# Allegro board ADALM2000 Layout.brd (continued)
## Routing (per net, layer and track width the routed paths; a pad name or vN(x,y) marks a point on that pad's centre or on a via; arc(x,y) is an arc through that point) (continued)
EN_SC2_CAL2: length 63.2
  TOP w0.102: U15.8 56.2,37.5 56.3,37.6 56.3,39.25 54.46,41.09 54.46,41.73 55.15,42.43 v1(55.15,42.87)
  L5_SIG w0.114: v1(24.48,52.91) 23.85,52.27 23.85,51.13 24.36,50.62 24.36,47.57 24.61,47.32 v1(24.61,46.68)
  L6_SIG w0.114: v1(55.15,42.87) 55.6,43.32 55.6,48.46 55.03,49.03 52.11,49.03 48.61,52.52 48.61,54.56 47.98,55.19 46.84,55.19 46.58,55.45 46.58,56.46 46.14,56.91 43.79,56.91 42.9,57.79 42.9,59.13 42.01,60.02 37.56,60.02 34.9,57.35 33.3,57.35 29.36,53.41 24.99,53.41 v1(24.48,52.91)
  BOTTOM w0.102: v1(24.61,46.68) 26.01,46.68 26.01,46.68 A2.16
EN_SC2_HG: length 56
  TOP w0.102: U15.14 53.35,35.85 51.85,37.35 51.85,41.41 v1(51.53,41.73) ; A1.9 29.81,47.71 v1(29.56,47.95) ; A1.1 v1(24.61,40.71)
  L5_SIG w0.114: v1(24.86,48.21) 25.12,47.95 25.12,41.22 v1(24.61,40.71)
  L6_SIG w0.114: v1(51.53,41.73) 50.65,42.62 50.65,45.41 50.01,46.05 48.87,46.05 47.22,47.7 47.22,49.1 45.82,50.49 41.5,50.49 39.85,52.14 38.96,52.14 37.95,53.16 30.96,53.16 30.26,52.46 30.26,50.68 29.31,49.73 29.31,48.71 29.56,48.46 v1(29.56,47.95) 29.18,47.57 25.5,47.57 v1(24.86,48.21)
EN_SC2_LG: length 49.3
  TOP w0.102: v1(23.47,47.57) 24.85,47.57 25.26,47.17 A1.16 ; v1(52.49,41.73) 52.49,41.29 52.17,40.97 52.17,37.41 53.33,36.25 U15.13
  TOP w0.203: A1.8 v1(29.81,41.92)
  L6_SIG w0.114: v1(52.49,41.73) 51.47,40.71 48.61,40.71 47.28,42.05 46.33,42.05 46.01,41.73 43.41,41.73 42.07,43.06 39.34,43.06 38.9,42.62 38.9,41.67 38.52,41.29 37.12,41.29 36.74,40.9 31.91,40.9 31.47,40.46 30.2,40.46 29.81,40.85 v1(29.81,41.92)
  BOTTOM w0.102: v1(23.47,47.57) 23.59,47.57 24.1,47.06 24.1,46.43 23.21,45.54 23.21,44.02 23.59,43.63 28.09,43.63 v1(29.81,41.92)
EN_SC_CAL1: length 65.6
  TOP w0.102: v1(54.2,43.51) 54.71,43 54.71,42.36 54.2,41.86 54.2,40.97 55.98,39.19 55.98,37.73 55.8,37.55 U15.9
  L6_SIG w0.114: v1(24.48,52.02) 25.37,52.91 29.44,52.91 33.5,56.97 35.02,56.97 37.69,59.64 41.88,59.64 42.52,59 42.52,57.6 43.53,56.59 45.95,56.59 46.2,56.33 46.2,55.32 46.71,54.81 47.85,54.81 48.23,54.43 48.23,52.4 52.55,48.08 52.55,47.44 51.53,46.43 51.53,44.52 52.55,43.51 v1(54.2,43.51)
  BOTTOM w0.102: A2.9 31.46,47.84 31.09,48.21 31.09,49.86 30.83,50.11 27.79,50.11 26.91,50.99 A2.1 24.99,52.52 v1(24.48,52.02)
EN_USR_POW_NEG: length 66
  TOP w0.102: U15.2 57.72,34.65 57.96,34.41 57.96,32.2 58.14,32.03 58.14,31.54 57.78,31.19 57.03,31.19 v1(56.61,30.77)
  L5_SIG w0.114: v1(56.61,30.77) 55.6,29.76 55.6,22.55 54.58,21.54 52.8,21.54 50.9,19.63 50.9,17.85 46.2,13.15 43.6,13.15 39.79,9.34 31.6,9.34 30.58,10.36 21.05,10.36 20.04,11.38 20.04,14.55 20.42,14.93 21.31,14.93 21.56,14.68 v1(24.36,14.68)
  BOTTOM w0.102: v1(24.36,14.68) 24.36,13.47 Q5.2
EN_USR_POW_POS: length 60.9
  TOP w0.102: v1(57.57,31.76) 57.57,32.33 57.35,32.55 U15.1
  L5_SIG w0.114: v1(20.67,14.3) 20.67,13.79 20.42,13.54 20.42,11.76 21.44,10.74 30.83,10.74 31.85,9.73 39.66,9.73 43.47,13.54 46.07,13.54 50.52,17.98 50.52,19.76 52.8,22.04 v1(53.31,22.04)
  BOTTOM w0.102: Q4.2 20.67,13.47 v1(20.67,14.3) ; v1(53.31,22.04) 54.58,23.31 58.65,23.31 58.96,23.63 58.96,27.7 57.69,28.97 57.69,31.32 v1(57.57,31.76)
ENABLE_POW_NEG: length 19.2
  TOP w0.102: A14.5 v1(15.4,5.92)
  BOTTOM w0.102: v1(15.4,5.92) 15.4,5.22 16.36,4.26 22.45,4.26 24.1,5.92 24.1,8.46 25.12,9.47 26.01,9.47 26.18,9.65 R147.1 26.18,12.33 Q5.3
ENABLE_POW_POS: length 13
  TOP w0.254: A12.5 v1(15.4,11.63)
  BOTTOM w0.102: v1(15.4,11.63) 15.4,10.68 16.1,9.98 20.93,9.98 22.32,11.38 22.32,12.15 Q4.3 22.88,12.71 R129.1
FB_1V0_D: length 12.5
  TOP w0.254: U6.32 v1(83.32,56.21)
  L5_SIG w0.305: v1(83.32,56.21) 83.32,49.69 84.17,48.84 v1(86.46,48.84)
  BOTTOM w0.203: v1(86.46,48.84) 85.87,48.84 R207.2
  BOTTOM w0.254: v1(83.32,56.21) 83.03,55.92 R208.1
FB_1V8: length 10.1
  TOP w0.203: U518.32 98.24,53.26 98.45,53.46 v2(98.45,54.05)
  L5_SIG w0.203: v1(98.91,47.06) 98.45,47.52 v2(98.45,54.05)
  BOTTOM w0.203: R765.1 98.4,46.22 98.4,46.56 v1(98.91,47.06) ; v2(98.45,54.05) R766.2
FB_1V35: length 16
  TOP w0.102: U518.9 92.84,53.26 92.68,53.41 v2(92.3,53.41)
  L5_SIG w0.203: v1(88.62,42.87) 89.38,42.87 93.44,46.94 93.44,52.65 92.68,53.41 v2(92.3,53.41)
  BOTTOM w0.102: R764.1 v2(92.3,53.41)
  BOTTOM w0.203: R763.2 v1(88.62,42.87)
FB_3V3_D: length 10.7
  TOP w0.254: U6.9 78.42,56.12 v1(78.33,56.21)
  L5_SIG w0.305: v1(75.86,49.22) 76.43,49.79 76.43,50.37 78.33,52.27 v1(78.33,56.21)
  BOTTOM w0.203: v1(75.86,49.22) 76.25,48.83 R205.2 ; R206.1 v1(78.33,56.21)
IN_SC1_N: length 15.1
  TOP w0.102: C72.1 18.32,56.72 R16.1 17.35,55.74 9.07,55.74 8.14,54.81 8.14,53.22 P1.1
IN_SC1_P: length 15
  TOP w0.102: P1.2 9.19,53.16 8.74,53.16 8.47,53.42 8.47,54.67 9.21,55.41 17.35,55.41 R19.1 18.32,54.43 C75.1
IN_SC2_N: length 15.3
  TOP w0.102: P1.3 8.25,49.02 8.43,49.02 8.97,48.49 11.63,48.49 16.65,43.47 17.39,43.47 18.07,42.78 R41.1 18.07,41.48 C129.1
IN_SC2_P: length 15.3
  TOP w0.102: P1.4 8.91,49.91 8.69,49.68 8.69,49.23 9.1,48.82 11.77,48.82 16.79,43.8 17.35,43.8 R44.1 18.32,44.78 C132.1
JTAG_TCK: length 35.4
  TOP w0.102: v1(60.3,6.17) 59.66,5.53 P510.4 ; U511.G9 82.03,25.93 77.84,21.74 77.69,21.74 76.33,20.38 75.61,20.38 69.66,14.42 66.52,14.42 v1(66.14,14.81)
  L5_SIG w0.114: v1(60.3,6.17) 61.69,6.17 63.73,8.2 63.73,10.36 64.74,11.38 64.74,13.41 v1(66.14,14.81)
JTAG_TDI: length 38.4
  TOP w0.102: v1(62.84,6.17) 62.2,5.53 P510.8 ; U511.L7 v2(85.99,27.62)
  L5_SIG w0.114: v2(85.99,27.62) 85.98,27.62 85.43,27.62 83.58,25.78 82.03,25.78 78.92,22.67 76.67,22.67 72.11,18.11 68.55,18.11 66.65,16.2 66.65,14.17 66.01,13.54 66.01,11 64.11,9.09 64.11,7.44 v1(62.84,6.17)
JTAG_TDO: length 39.3
  TOP w0.102: P510.6 60.93,6.8 v1(62.84,8.71) ; 84.85,28.19 v2(85.42,28.19)
  L5_SIG w0.114: v1(62.84,8.71) 62.84,9.98 64.36,11.5 64.36,14.46 72.59,22.68 73.63,22.68 74.01,22.3 74.78,22.3 75.66,23.19 76.43,23.19 76.55,23.06 78.88,23.06 81.89,26.06 82.73,26.06 84.86,28.19 85.42,28.19 v2(85.42,28.19)
JTAG_TMS: length 41.3
  TOP w0.102: P510.2 58.39,6.8 v1(60.3,8.71) ; U511.L9 v2(84.85,28.75)
  L5_SIG w0.114: v2(84.85,28.75) 83.16,28.75 77.72,23.31 76.81,23.31 76.05,24.08 74.39,24.08 73.79,23.47 72.84,23.47 63.98,14.61 63.98,12.9 62.2,11.12 62.2,9.47 61.44,8.71 v1(60.3,8.71)
LOOP_FILT: length 12.8
  TOP w0.203: v1(67.54,57.73) 67.32,57.51 U14.24
  TOP w0.305: R86.1 70.08,63.62 C223.1 70.15,64.67 R6.1 v1(71.09,63.95)
  BOTTOM w0.305: v1(67.54,57.73) 67.54,62.68 68.81,63.95 v1(71.09,63.95)
MASTER_CLK_N: length 15.5
  TOP w0.102: C237.2 73.84,60.45 74.34,59.94 74.34,58.81 70.59,55.06 67.19,55.06 66.59,54.46 U2.56
MASTER_CLK_P: length 15.4
  TOP w0.102: C236.2 73.02,59.59 73.12,59.69 73.12,60.02 73.23,60.12 73.7,60.12 74.01,59.8 74.01,58.95 70.46,55.4 67.05,55.4 66.26,54.6 66.26,52.34 66.09,52.17 U2.57
MUX_EN: length 17.9
  TOP w0.102: v1(34.25,36.01) 35.02,36.01 36.37,37.36 R47.2
  L5_SIG w0.114: v1(34.9,44.52) 35.28,44.14 35.28,36.4 34.9,36.01 v1(34.25,36.01)
  BOTTOM w0.102: U9.16 34.81,35.97 34.78,36 34.26,36 v1(34.25,36.01) ; U8.16 35.7,46.6 34.9,45.79 v1(34.9,44.52)
OFFSET_AWG1: length 3.3
  BOTTOM w0.102: U11.4 35.91,30.93 35.62,31.22 R99.1
OFFSET_AWG2: length 14.5
  TOP w0.203: v1(41.37,31.57) 42.01,32.2 42.01,32.71 41.31,33.41 41.31,35.89 40.3,36.9 36.55,36.9 35.24,35.6 R100.1
  BOTTOM w0.203: v1(41.37,31.57) 41.37,31.19 41.63,30.93 U11.11
OFFSET_SC1: length 54.8
  TOP w0.102: v2(40.36,32.59) 39.98,32.2 39.98,30.17 41.17,28.98 42.82,28.98 44.8,27 46.84,27 47.22,27.38 47.22,28.14 48.27,29.19 A6.1 48.6,29.68 48.92,29.36 R127.2 50.38,29.36 C304.2 ; R29.1 40.85,59.07 v1(40.21,59.07)
  L5_SIG w0.102: OFF_SC1.1 40.21,60.63 v1(40.21,59.07)
  L5_SIG w0.114: v1(40.21,59.07) 39.66,58.52 39.66,56.14 40.1,55.7 40.1,49.86 39.6,49.35 39.6,48.27 40.74,47.13 40.74,44.14 40.1,43.51 39.22,43.51 38.64,42.94 38.64,39.44 36.93,37.73 36.93,34.24 36.74,34.05 36.74,32.9 37.69,31.95 39.72,31.95 v2(40.36,32.59)
OFFSET_SC2: length 48.6
  TOP w0.102: R54.1 40.66,44.27 v1(40.1,44.27) ; A6.7 44.43,30.18 43.99,29.74 R128.2 43.03,29.74 C305.2 42.65,29.36 41.3,29.36 40.36,30.3 v2(40.36,31.57)
  L5_SIG w0.114: v2(40.36,31.57) 37.56,31.57 36.42,32.71 36.42,34.24 36.61,34.43 36.61,37.92 38.33,39.63 38.33,43.13 39.04,43.84 39.68,43.84 v1(40.1,44.27) 39.6,44.78 39.09,44.78 38.45,44.14 37.95,44.14 37.63,44.46 37.63,48.91 39.72,51 39.72,51.64 39.34,52.02 38.96,52.02 38.58,52.4 38.58,54.56 38.96,54.94 38.96,61.67 OFF_SC2.1
OUT_AWG1: length 26.1
  TOP w0.305: 24.04,25.85 23.99,25.81 R135.1 21.61,25.81 20.8,26.62 20.8,35.38 19.09,37.09 16.29,37.09 11.1,42.29 P1.10
OUT_AWG1_CALIB: length 35
  TOP w0.203: R197.1 R135.2 v1(22.83,26.67)
  L5_SIG w0.114: v1(22.83,26.67) 21.18,28.32 21.18,34.81 24.61,38.24 24.61,39.57 25.5,40.46 25.5,46.68 29.18,50.37 v1(32.74,50.37)
  BOTTOM w0.102: U8.3 34.06,49.8 33.5,50.37 v1(32.74,50.37)
OUT_AWG2: length 24.1
  TOP w0.305: P1.9 8.59,43.51 12.55,43.51 17.63,38.43 19.53,38.43 21.94,36.01 21.94,34.11 22.2,33.86 R134.1 22.72,33.08 23.47,32.33 23.47,31.82 R133.2
OUT_AWG2_CALIB: length 24.1
  TOP w0.203: v1(22.83,32.22) R134.2 R198.1
  BOTTOM w0.102: v1(22.83,32.22) 21.12,33.93 21.12,34.81 23.34,37.03 23.34,40.59 23.98,41.22 25.37,41.22 26.01,40.59 28.8,40.59 29.06,40.33 29.06,39.19 29.25,39 32.23,39 33.24,37.99 U9.3
PG_1P0V: length 21.7
  TOP w0.203: U6.29 83.92,54.04 84.05,54.18 85.06,54.18 v1(85.32,53.92) ; v2(99.92,51.76) 99.42,51.26 U518.28
  TOP w0.254: R89.2 v1(85.32,53.92)
  L6_SIG w0.114: v1(85.32,53.92) 86.46,53.92 87.09,54.56 93.51,54.56 93.95,54.11 97.57,54.11 98.08,53.6 98.08,52.65 98.43,52.3 99.38,52.3 v2(99.92,51.76)
PG_1P8V: length 135.3
  TOP w0.102: U12.3 45.95,11.06 v2(46.07,11.38) ; v2(55.34,20.9) 55.09,20.64 U10.6 ; U7.3 v1(36.55,15.44)
  TOP w0.203: v2(91.29,51.76) 91.79,51.26 U518.13 ; U6.13 77.44,53.54 77.32,53.67 75.28,53.67 74.52,54.43 v1(74.52,55.45) ; v2(99.16,51.76) 99.16,51.76 U518.29
  L5_SIG w0.114: v2(55.34,20.9) 54.77,20.33 52.11,20.33 51.28,19.5 51.28,17.69 46.07,12.49 v2(46.07,11.38) ; v2(82.9,38.55) 82.9,39.32 85.06,41.48 85.06,46.3 86.08,47.32 87.22,47.32 88.49,48.59 88.49,50.94 89.32,51.76 v2(91.29,51.76)
  L6_SIG w0.114: v2(46.07,11.38) 45.63,11.82 42.39,11.82 39.85,9.28 34.9,9.28 33.63,10.55 33.63,12.52 v1(36.55,15.44) ; v1(74.52,55.45) 76.93,55.45 78.08,54.3 78.08,52.52 79.35,51.25 90.78,51.25 v2(91.29,51.76) 91.79,52.27 92.75,52.27 94.08,53.6 97.32,53.6 97.64,53.29 97.64,52.52 98.4,51.76 v2(99.16,51.76)
  BOTTOM w0.102: v2(82.9,38.55) 81.95,38.55 80.58,39.93 75.26,39.93 74.84,39.51 74.84,37.67 70.83,33.65 68.22,33.65 66.27,31.7 66.27,31.19 66.77,30.68 66.77,28.14 60.93,22.3 58.01,22.3 56.61,20.9 v2(55.34,20.9)
  BOTTOM w0.203: v2(99.16,51.76) 98.83,51.43 R750.1
PS-SRST#: length 28.5
  TOP w0.102: v2(68.16,4.26) U508.A4 ; 78.07,24.79 78.07,24.24 75.37,21.54 74.9,21.54 74.52,21.92 74.14,21.92 R791.2 74.07,21.32 74.07,20.96 70.84,17.73 69.44,17.73 68.43,16.71 v1(68.43,16.2)
  L5_SIG w0.114: v2(68.16,4.26) 67.16,5.26 67.16,12.7 68.43,13.97 v1(68.43,16.2)
PS_MIO01_500_QSPI0_SS_B: length 31
  TOP w0.102: U511.A5 80.46,20.4 80.46,19.31 77.68,16.52 77.68,15.62 78.8,14.51 78.8,13.62 76.43,11.25 v1(75.41,11.25) ; 70.7,6.8 v2(71.2,6.3)
  L5_SIG w0.114: v2(71.2,6.3) 71.5,6.61 71.5,6.82 71.15,7.16 71.15,7.37 71.3,7.52 71.51,7.52 72.11,6.92 72.32,6.92 72.47,7.07 72.47,7.28 71.87,7.88 71.87,8.09 72.02,8.24 72.23,8.24 72.83,7.64 73.04,7.64 73.19,7.79 73.19,8 72.59,8.6 72.59,8.81 72.74,8.96 72.95,8.96 73.55,8.36 73.76,8.36 73.91,8.51 73.91,8.72 73.31,9.32 73.31,9.53 73.46,9.68 73.67,9.68 74.27,9.08 74.48,9.08 74.63,9.23 74.63,9.44 74.03,10.04 74.03,10.25 74.18,10.4 74.39,10.4 74.93,9.85 75.16,9.85 75.41,10.11 v1(75.41,11.25)
  BOTTOM w0.102: R586.2 72.05,6.3 v2(71.2,6.3)
PS_MIO02_500_QSPI0_IO0: length 27
  TOP w0.102: U511.A8 78.14,21.47 77.96,21.47 76.42,19.93 76.42,19.75 72.11,15.44 v1(71.6,15.44) ; U508.D3 v2(70.2,8.3)
  L5_SIG w0.114: v1(71.6,15.44) 71.98,15.06 71.98,14.3 71.22,13.54 71.22,13.14 71.07,12.99 70.73,12.99 70.58,12.84 70.58,12.63 70.73,12.48 71.07,12.48 71.22,12.33 71.22,12.12 71.07,11.97 70.73,11.97 70.58,11.82 70.58,11.61 70.73,11.47 71.96,11.47 72.11,11.32 72.11,11.11 71.96,10.96 70.73,10.96 70.58,10.81 70.58,10.6 70.73,10.45 71.07,10.45 71.22,10.3 71.22,9.85 70.84,9.47 69.44,9.47 69.19,9.22 69.19,8.46 69.34,8.3 v2(70.2,8.3)
  BOTTOM w0.102: R593.1 70.2,9.05 v2(70.2,8.3)
PS_MIO03_500_QSPI0_IO1: length 31.2
  TOP w0.102: U511.A7 79.16,21.96 v2(78.24,21.05) ; U508.D2 v2(71.2,8.3)
  L5_SIG w0.114: v2(71.2,8.3) 73.63,10.74 73.63,11.1 73.78,11.25 74.25,11.25 74.39,11.39 74.39,11.61 74.25,11.75 73.78,11.75 73.63,11.9 73.63,12.11 73.78,12.26 74.25,12.26 74.39,12.41 74.39,12.62 74.25,12.77 73.78,12.77 73.63,12.92 73.63,13.13 73.78,13.28 74.25,13.28 74.39,13.43 74.39,13.64 74.25,13.79 73.78,13.79 73.63,13.93 73.63,14.42 74.01,14.81 77.7,14.81 77.86,14.97 77.86,15.21 77.71,15.36 76.84,15.36 76.69,15.51 76.69,15.72 76.84,15.87 77.71,15.87 77.86,16.01 77.86,16.22 77.71,16.37 76.84,16.37 76.69,16.52 76.69,16.73 76.84,16.88 77.71,16.88 77.86,17.03 77.86,17.24 77.71,17.39 76.84,17.39 76.69,17.54 76.69,17.75 76.84,17.9 77.71,17.9 77.86,18.05 77.86,19.4 78.67,20.2 78.67,20.63 v2(78.24,21.05)
  BOTTOM w0.102: R594.1 71.2,9.07 v2(71.2,8.3)
PS_MIO04_500_QSPI0_IO2: length 30.1
  TOP w0.102: U511.C8 v2(80.9,23.66) ; U508.C4 v2(68.31,7.19)
  L5_SIG w0.114: v2(68.31,7.19) 68.68,7.57 70.46,7.57 70.71,7.82 70.71,8.58 73.12,11 73.12,13.54 72.98,13.69 72.51,13.69 72.36,13.84 72.36,14.05 72.51,14.2 72.98,14.2 73.12,14.35 73.12,14.81 73.94,15.63 74.93,15.63 75.08,15.77 75.08,15.98 74.93,16.13 73.97,16.13 73.82,16.28 73.82,16.49 73.97,16.64 74.93,16.64 77.05,18.77 77.05,20.56 78.03,21.54 79.64,21.54 80.9,22.79 v2(80.9,23.66)
  BOTTOM w0.102: v2(68.31,7.19) 69,7.19 R590.1 68.31,7.19 v2(68.31,7.19)
PS_MIO05_500_QSPI0_IO3: length 41
  TOP w0.102: v1(65.38,8.71) 66.52,7.57 66.52,3.76 64.62,1.85 61.19,1.85 60.93,2.11 P510.5 ; U511.A9 76.18,20.65 75.34,20.65 71.28,16.58 70.97,16.58 v1(70.58,16.2) ; U508.D4 v2(68.2,8.3)
  L5_SIG w0.114: v2(68.2,8.3) 68.2,8.79 68.34,8.94 68.53,8.94 68.68,9.09 68.68,9.3 68.53,9.44 68.34,9.44 68.2,9.59 68.2,9.8 68.34,9.95 68.53,9.95 68.68,10.1 68.68,10.31 68.53,10.46 68.34,10.46 68.2,10.61 68.2,11.15 68.34,11.29 69.93,11.29 70.08,11.44 70.08,11.65 69.93,11.8 68.34,11.8 68.2,11.95 68.2,12.29 70.58,14.68 v1(70.58,16.2)
  BOTTOM w0.102: v1(65.38,8.71) 66.14,8.71 66.57,8.28 R591.1 67.56,8.3 v2(68.2,8.3)
PS_MIO06_500_QSPI0_SCLK: length 28.2
  TOP w0.102: v1(69.06,15.31) 69.06,16.71 69.7,17.35 70.96,17.35 74.77,21.16 75.56,21.16 U511.A10 ; U508.B2 v2(71.2,5.3)
  L5_SIG w0.114: v2(71.2,5.3) 69.93,5.3 69.19,6.04 68.3,6.04 67.66,6.68 67.66,12.52 69.06,13.92 v1(69.06,15.31)
  BOTTOM w0.102: R583.1 72.04,5.3 v2(71.2,5.3)
PS_MIO07_500_USB_RESET_B: length 27.8
  TOP w0.102: 76.94,24.79 v2(76.45,24.31) ; U524.27 61.83,28.22 61.57,27.95 61.57,26.74 63.35,24.97 65.57,24.97 67.73,22.81 67.73,20.08 v1(68.04,19.76)
  L6_SIG w0.114: v1(68.04,19.76) 69.57,18.23 70.97,18.23 76.45,23.72 v2(76.45,24.31)
  BOTTOM w0.102: v2(76.45,24.31) 76.91,24.77 R798.2
PS_MIO28_501_USB0_D4: length 23
  TOP w0.102: U511.A15 74.79,26.04 73.56,26.04 72.74,25.22 68.93,25.22 68.3,25.85 v2(67.16,25.85) ; v2(65.81,33.47) 65.05,33.47 U524.7
  L5_SIG w0.114: v2(67.16,25.85) 67.16,26.36 66.77,26.74 66.77,30.81 66.27,31.32 66.27,32.59 65.89,32.97 65.39,32.97 65.24,33.11 65.24,33.46 65.1,33.6 64.89,33.6 64.75,33.46 64.75,33.11 64.6,32.97 64.36,32.97 64.23,33.09 64.23,33.98 64.36,34.11 65.63,34.11 65.81,33.93 v2(65.81,33.47)
PS_MIO29_501_USB0_DIR: length 29.2
  TOP w0.102: U511.D11 78.66,25.92 78.2,25.47 77.95,25.47 77.7,25.73 77.32,25.73 75.66,24.08 74.52,24.08 73.76,23.31 68.68,23.31 v2(68.17,23.82) ; U524.31 63.83,28.92 v2(64.11,28.65)
  L5_SIG w0.114: v2(68.17,23.82) 68.17,24.2 67.92,24.46 67.79,24.46 67.54,24.2 67.54,23.19 67.28,22.93 67.04,22.93 66.9,23.08 66.9,23.93 66.75,24.08 66.55,24.08 66.4,23.93 66.4,23.08 66.26,22.93 66.01,22.93 65.89,23.06 65.89,24.08 64.5,25.46 64.5,25.79 65.31,26.6 65.31,26.81 65.17,26.95 64.96,26.95 64.15,26.14 63.95,26.14 63.73,26.36 63.73,26.62 64.43,27.32 64.43,28.33 v2(64.11,28.65)
PS_MIO30_501_USB0_STP: length 24
  TOP w0.102: v2(62.96,28.08) 62.83,28.21 U524.29 ; U511.B15 75.48,27.38 74.79,27.38 74.28,26.87 73.38,26.87 72.49,25.98 69.19,25.98 68.3,26.87 67.54,26.87 66.97,27.44 64.55,27.44 64.36,27.25 64.36,26.05 64.04,25.73 v2(63.6,25.73)
  L5_SIG w0.114: v2(62.96,28.08) 62.84,28.2 62.84,29.28 62.58,29.54 62.08,29.54 61.82,29.28 61.82,26.49 62.58,25.73 v2(63.6,25.73)
PS_MIO31_501_USB0_NXT: length 29.4
  TOP w0.102: v2(66.27,25.85) 66.65,25.47 66.65,25.22 66.39,24.97 66.14,24.97 65.63,25.47 64.81,25.47 64.68,25.6 64.68,27 64.81,27.12 65.02,27.12 65.16,26.98 65.16,26.12 65.3,25.98 65.44,25.98 65.58,26.12 65.58,26.98 65.72,27.12 65.89,27.12 66.03,26.98 66.03,26.5 66.17,26.36 66.37,26.36 66.51,26.5 66.51,26.98 66.65,27.12 66.84,27.12 66.97,27 66.97,26.49 67.09,26.36 68.3,26.36 69.06,25.6 72.62,25.6 73.51,26.49 74.52,26.49 75.03,27 75.28,27 75.66,26.62 75.92,26.62 76.11,26.81 76.62,26.81 77.32,26.11 77.88,26.11 U511.C12 ; v2(66.33,30.49) 65.87,30.95 U524.2
  L5_SIG w0.114: v2(66.27,25.85) 66.33,25.92 v2(66.33,30.49)
PS_MIO32_501_USB0_D0: length 17
  TOP w0.102: v2(65.81,29.79) 66.57,29.03 67.18,29.03 67.32,29.17 67.32,29.52 67.46,29.66 67.66,29.66 67.8,29.52 67.8,29.17 67.94,29.03 68.14,29.03 68.28,29.17 68.28,29.52 68.43,29.66 68.63,29.66 68.77,29.52 68.77,29.17 68.91,29.03 70.97,29.03 71.6,29.66 75.28,29.66 75.59,29.36 76.89,29.36 U511.E15 ; U524.3 v2(65.81,31.45)
  L5_SIG w0.114: v2(65.81,31.45) v2(65.81,29.79)
PS_MIO33_501_USB0_D1: length 30.5
  TOP w0.102: v2(68.18,31.45) 67.66,30.93 66.52,30.93 66.27,31.19 66.27,31.57 65.88,31.95 U524.4 ; v2(68.17,22.81) 73.51,22.81 73.89,22.43 74.65,22.43 76.02,23.79 76.45,23.79 77.88,25.22 78.09,25.22 78.22,25.09 78.37,25.09 U511.C11
  L5_SIG w0.114: v2(68.18,31.45) 68.18,31.43 68.68,30.93 68.68,30.59 68.82,30.45 69.17,30.45 69.31,30.3 69.31,30.1 69.17,29.95 68.82,29.95 68.68,29.81 68.68,29.6 68.82,29.46 69.17,29.46 69.31,29.31 69.31,29.11 69.17,28.96 68.82,28.96 68.68,28.82 68.68,28.61 68.82,28.47 69.55,28.47 69.7,28.32 69.7,28.12 69.55,27.97 68.82,27.97 68.68,27.83 68.68,27.62 68.82,27.48 69.55,27.48 69.7,27.33 69.7,27.13 69.55,26.98 68.82,26.98 68.68,26.84 68.68,26.49 68.93,26.24 68.93,25.98 68.68,25.73 68.68,23.31 v2(68.17,22.81)
PS_MIO34_501_USB0_D2: length 20.1
  TOP w0.102: v2(65.76,28.78) 66.14,28.78 66.27,28.65 70.97,28.65 71.6,29.28 75.03,29.28 75.51,28.81 76.32,28.81 76.94,28.19 ; v2(65.81,32.45) U524.5
  L5_SIG w0.114: v2(65.76,28.78) 65.76,29.22 65.38,29.6 65.38,30.18 65.23,30.33 64.58,30.33 64.43,30.47 64.43,30.68 64.58,30.82 65.23,30.82 65.38,30.97 65.38,31.17 65.23,31.32 64.58,31.32 64.43,31.46 64.43,32.28 64.61,32.45 v2(65.81,32.45)
PS_MIO35_501_USB0_D3: length 25.8
  TOP w0.102: U511.A14 75.2,25.32 73.86,25.32 73,24.46 68.55,24.46 v2(68.17,24.84) ; v2(66.77,31.44) 66.77,31.95 66.9,32.08 68.43,32.08 68.68,32.33 68.68,32.71 68.44,32.95 U524.6
  L5_SIG w0.114: v2(68.17,24.84) 68.17,25.85 67.16,26.87 67.16,27.95 67.3,28.1 67.77,28.1 67.92,28.24 67.92,28.45 67.77,28.59 67.3,28.59 67.16,28.74 67.16,28.94 67.3,29.09 67.77,29.09 67.92,29.23 67.92,29.44 67.77,29.58 67.3,29.58 67.16,29.73 67.16,29.93 67.3,30.08 67.77,30.08 67.92,30.22 67.92,30.43 67.77,30.58 67.3,30.58 67.16,30.72 67.16,31.06 v2(66.77,31.44)
PS_MIO36_501_USB0_CLK: length 22.6
  TOP w0.102: v2(65.19,28.78) 65.19,29.09 65.38,29.28 65.38,30.3 65.22,30.45 U524.1 ; v2(67.16,24.84) 67.66,25.35 68.3,25.35 68.81,24.84 72.87,24.84 73.71,25.68 74.98,25.68 75.59,26.29 76.17,26.29 U511.B14
  L5_SIG w0.114: v2(65.19,28.78) 64.23,29.73 64.23,30.05 63.98,30.3 63.73,30.3 63.47,30.05 63.47,29.41 63.66,29.22 64.11,29.22 65.16,28.17 65.16,27.73 65.63,27.25 65.63,25.6 66.65,24.58 66.9,24.58 v2(67.16,24.84)
PS_MIO37_501_USB0_D5: length 23.2
  TOP w0.102: v2(67.66,27.38) 68.43,27.38 69.44,26.36 70.97,26.36 71.35,26.74 71.35,27.25 71.85,27.76 75.71,27.76 76.22,27.25 76.74,27.25 U511.C14 ; U524.9 64.33,34.97 64.62,35.25 65.12,35.25 v2(65.76,34.62)
  L5_SIG w0.114: v2(67.66,27.38) 67.66,26.87 67.95,26.58 68.14,26.58 68.3,26.74 68.3,30.68 67.41,31.57 67.41,31.95 66.27,33.09 66.27,34.11 v2(65.76,34.62)
PS_MIO38_501_USB0_D6: length 29.9
  TOP w0.102: v2(69.19,23.82) 69.44,24.08 73.13,24.08 74.01,24.96 75.41,24.96 75.8,25.36 U511.A13 ; v2(63.92,35.51) 63.83,35.17 U524.10
  L5_SIG w0.114: v2(69.19,23.82) 69.7,24.33 69.7,25.16 69.55,25.3 69.33,25.3 69.19,25.45 69.19,25.65 69.33,25.8 70.57,25.8 70.71,25.94 70.71,26.15 70.57,26.29 70.27,26.29 70.08,26.49 70.08,26.49 70.08,28.78 69.7,29.16 69.7,30.55 68.04,32.2 67.66,32.2 66.65,33.22 66.65,34.11 66.27,34.49 66.27,35.25 66.77,35.76 66.77,36.14 66.52,36.4 65.64,36.4 65.5,36.25 65.5,35.91 65.35,35.76 65.15,35.76 65,35.91 65,36.25 64.86,36.4 64.36,36.4 63.92,35.95 v2(63.92,35.51)
PS_MIO39_501_USB0_D7: length 21.2
  TOP w0.102: v2(66.77,34.62) 65.38,36.01 62.71,36.01 62.52,35.82 62.52,35.38 62.33,35.19 U524.13 ; U511.D14 76.89,27.62 76.1,28.41 74.79,28.41 74.65,28.27 v2(71.21,28.27)
  L5_SIG w0.114: v2(66.77,34.62) 67.03,34.36 67.03,33.35 67.66,32.71 68.04,32.71 70.08,30.68 70.08,29.4 v2(71.21,28.27)
PWR_GD_1.35V: length 53.2
  TOP w0.102: U511.C9 v2(79.2,24.23)
  TOP w0.203: v2(92.05,51.76) U518.12
  L6_SIG w0.114: v1(69.55,16.19) 70.59,17.22 71.47,17.22 78.48,24.23 v2(79.2,24.23) 79.2,24.82 81.89,27.51 82.4,27.51 85.44,30.55 85.44,31.7 87.6,33.86 90.65,33.86 91.41,34.62 91.41,35.25 91.92,35.76 91.92,42.62 92.81,43.51 92.81,51 v2(92.05,51.76)
  BOTTOM w0.102: v1(69.55,16.19) 70.09,15.66 R587.1 70.1,15.32 69,14.22 R585.2
PWR_GOOD: length 95
  TOP w0.102: v1(56.61,31.76) 56.17,31.76 55.92,31.51 54.84,31.51 53.95,32.4 53.95,33.35 54.1,33.5 U15.19 ; v2(35.53,10.61) 36.29,10.61 36.55,10.87 U7.6 ; v1(57.25,19.25) 56.86,18.87 U10.3
  TOP w0.203: v1(76.05,54.18) 77.44,54.18 77.57,54.04 U6.12
  L5_SIG w0.114: v1(58.39,39.44) 57.76,40.08 57.12,40.08 56.74,39.7 56.74,35.89 57.21,35.42 57.21,32.35 v1(56.61,31.76) 56.61,31.7 57.31,31 57.31,28.71 58.27,27.76 58.27,25.09 57.88,24.71 57.88,22.17 57.25,21.54 v1(57.25,19.25)
  L6_SIG w0.114: v2(35.53,10.61) 38.92,10.61 41.12,12.82 41.12,15.95 41.88,16.71 49.38,16.71 50.87,18.21 50.87,19.61 51.66,20.39 56.11,20.39 v1(57.25,19.25) ; v1(58.39,39.44) 57.57,40.27 57.57,41.73 58.65,42.81 58.65,50.87 59.03,51.25 67.28,51.25 68.27,52.24 70.17,52.24 71.47,53.54 75.41,53.54 v1(76.05,54.18)
  BOTTOM w0.203: v2(35.53,10.61) 35.53,9.7 R155.2
REF_1V0_AWG: length 41.4
  TOP w0.203: v1(63.09,52.5) 63.09,52.49 U2.63
  TOP w0.305: v1(49.63,28.39) 50.69,28.39 R143.2
  L5_SIG w0.203: v1(63.09,52.5) 63.7,51.89 65.63,51.89 66.58,50.94 66.58,43.44 66.14,43 57.38,43 54.9,40.52 54.9,37.16 52.42,34.68 52.42,31.19 v1(49.63,28.39)
  BOTTOM w0.305: v1(63.09,52.5) C62.1
REF_1V2: length 60.9
  TOP w0.305: A8.3 48.86,35.76 49.12,36.01 v1(49.12,36.14) ; v1(44.23,36.26) A8.5 ; C97.1 v1(25.88,21.92) 25.37,21.92 25.1,21.65 U20.10
  L5_SIG w0.508: v1(31.72,24.84) 31.72,25.85 ; 31.72,25.85 32.23,26.36 v1(32.87,26.36) 33.37,26.36 33.88,26.87 33.88,32.46 34.26,32.84 v1(34.64,32.84) ; 31.72,25.85 30.33,25.85 28.67,24.2 27.53,24.2 27.02,23.7 27.02,22.3 26.64,21.92 v1(25.88,21.92) 25.63,21.66 23.09,21.66 22.45,22.3 v1(20.42,22.3) 20.04,21.92 20.04,20.52 21.05,19.5 v1(21.05,18.23)
  L6_SIG w0.635: v1(44.23,36.26) 42.85,34.87 37.44,34.87 35.41,32.84 v1(34.64,32.84)
  BOTTOM w0.305: v1(34.64,32.84) 34.71,32.78 C296.1 35.39,32.88 U11.7 ; v1(20.42,22.3) 20.71,22.59 A13.5 ; v1(21.05,18.23) 21.57,18.75 A13.3 ; 31.41,25.16 C291.1 32.04,25.85 ; 31.81,24.2 C293.1 31.41,24.66
  BOTTOM w0.406: U19.6 32.94,25.89 ; U19.6 33.69,25.28 ; U19.6 U19.5 ; U19.6 32.19,25.28 ; U19.5 33.69,24.33 ; U19.5 32.19,24.33
  BOTTOM w0.508: v1(44.23,36.26) 44.92,36.26 45.69,37.03 48.23,37.03 v1(49.12,36.14)
REF_1V2_SC: length 70.7
  TOP w0.305: R115.1 55.08,30.81 v1(55.54,30.81)
  L5_SIG w0.508: v1(55.54,30.81) 54.71,29.98 v1(54.71,25.79)
  L5_SIG w0.635: v1(39.98,25.22) v1(39.34,25.22) 39.34,26.05 39.03,26.36 39.03,28.74 35.66,32.1 35.66,33.22 34.9,33.98 32.99,33.98 29.5,37.48 29.5,38.68 30.01,39.19 30.83,39.19 31.47,39.82 v1(31.47,41.35)
  L6_SIG w0.508: v1(54.71,25.79) 49.19,25.79 47.45,24.05 46.23,24.05 45.06,25.22 v1(39.98,25.22) v1(39.34,25.22) ; v1(31.47,41.35) 31.47,47.57 32.36,48.46 35.66,48.46 v1(38.45,51.25)
  BOTTOM w0.305: 39.04,23.76 C292.1 38.58,24.17 ; v1(38.45,51.25) 38.45,51.64 38.71,51.89 39.8,51.89 R81.1 ; R79.1 31.6,40.97 31.47,41.09 v1(31.47,41.35)
  BOTTOM w0.406: U18.5 U18.6 ; U18.5 41.05,23.44 ; U18.5 40.17,23.57 39.47,23.57 ; U18.6 41.05,24.39 ; U18.6 40.3,25 ; U18.6 39.55,24.39
  BOTTOM w0.635: 39.91,25.41 C289.1 39.28,26.11
REF_AWG1: length 14.7
  TOP w0.102: R97.1 v1(32.87,21.41)
  BOTTOM w0.203: A13.2 22.07,18.75 22.2,18.62 22.45,18.62 22.57,18.73 A13.1 22.6,19.5 24.61,19.5 26.64,21.54 29.56,21.54 30.07,21.03 32.48,21.03 v1(32.87,21.41)
REF_AWG2: length 19.4
  TOP w0.203: R98.1 32.23,31.7 31.98,31.44 29.31,31.44 v1(28.8,30.93)
  L6_SIG w0.203: v1(28.8,30.93) 28.04,30.17 23.34,30.17 v1(22.58,29.41)
  BOTTOM w0.203: A13.7 22.07,23.19 21.94,23.31 ; 21.94,23.31 21.69,23.31 21.57,23.19 A13.6 ; 21.94,23.31 21.94,25.22 21.69,25.47 21.69,28.01 22.58,28.9 v1(22.58,29.41)
REF_SC1: length 37.5
  TOP w0.102: A8.7 44.36,35.26 44.17,35.06 44.17,34.7 R125.2 42.65,34.06 C302.2 42.26,33.67 v1(41.88,33.67) ; v1(40.23,56.4) 40.85,56.4 R28.1
  L5_SIG w0.114: v1(40.23,56.4) 40.49,56.14 40.49,49.52 39.98,49.01 39.98,48.46 41.12,47.32 41.12,43.89 40.36,43.13 39.47,43.13 38.96,42.62 38.96,39.25 37.18,37.48 37.18,34.11 37.06,33.98 37.06,33.09 37.82,32.33 39.47,32.33 40.31,33.17 40.31,33.8 40.61,34.11 41.44,34.11 v1(41.88,33.67)
REF_SC2: length 25.2
  TOP w0.102: 48.46,34.76 49.31,34.76 R126.2 50.38,34.57 C303.2 ; 48.46,34.76 A8.1 ; 48.46,34.76 48.49,34.73 48.49,34.36 v1(48.74,34.11) ; v1(43.53,48.46) 42.9,47.83 40.99,47.83 40.87,47.7 R55.1
  L5_SIG w0.114: v1(43.53,48.46) 44.17,48.46 44.42,48.21 46.07,48.21 48.23,46.05 48.23,43.76 48.87,43.13 48.87,37.92 47.85,36.9 47.85,35 v1(48.74,34.11)
RX_CLK: length 11.1
  TOP w0.102: U511.N11 v2(84.29,31.58)
  BOTTOM w0.102: v2(84.29,31.58) 84.79,32.08 84.94,32.08 85.19,31.82 85.57,31.82 85.7,31.95 85.7,32.33 85.44,32.59 85.44,32.84 85.82,33.22 85.82,33.98 86.08,34.24 86.59,34.24 86.84,34.49 86.84,36.65 86.59,36.9 86.08,36.9 85.57,36.4 85.32,36.4 84.94,36.78 84.94,36.97 R173.1
RXCML: length 25.3
  TOP w0.102: v1(49.88,48.33) 50.26,48.71 53.44,48.71 54.2,47.95 55.47,47.95 56.11,47.32 56.11,46.75 C65.1 56.43,46.42 57.21,46.42 57.35,46.56 U2.10
  L5_SIG w0.114: v1(48.61,56.21) 48.61,53.92 48.99,53.54 48.99,49.98 49.88,49.1 v1(49.88,48.33) 48.61,48.33 48.23,47.95 48.23,46.68 48.74,46.17 v1(48.74,44.27)
  BOTTOM w0.102: v1(48.74,44.27) 48.74,43.59 R62.2
  BOTTOM w0.203: v1(48.61,56.21) 48.61,56.92 R36.2
RXD_0: length 4.7
  TOP w0.102: U511.P10 85.42,31.61 86.33,32.52 v2(86.33,34.74)
  BOTTOM w0.102: R188.2 v2(86.33,34.74)
RXD_1: length 10.7
  TOP w0.102: v2(82.9,36.65) 83.54,37.28 86.21,37.28 86.84,36.65 86.84,32.44 U511.R10
  BOTTOM w0.102: R187.2 82.65,36.9 v2(82.9,36.65)
RXD_2: length 7.7
  TOP w0.102: U511.P8 87.06,29.88 87.86,30.68 88.24,30.68 90.27,32.71 90.27,34.36 v2(89.89,34.74)
  BOTTOM w0.102: v2(89.89,34.74) R186.2
RXD_3: length 6.4
  TOP w0.102: v2(88.87,34.74) 87.64,33.51 87.64,31.53 86.55,30.45 U511.P9
  BOTTOM w0.102: R185.2 v2(88.87,34.74)
RXD_4: length 10.7
  TOP w0.102: v2(87.12,28.75) U511.N7
  BOTTOM w0.102: R184.2 88.36,36.84 88.36,34.49 86.97,33.09 86.97,32.71 87.86,31.82 87.86,30.93 86.97,30.05 86.97,29.16 v2(87.12,28.75)
RXD_5: length 7.8
  TOP w0.102: v2(86.55,29.32) U511.N8
  BOTTOM w0.102: R183.2 87.86,34.36 86.71,33.22 86.71,32.59 87.6,31.7 87.6,31.06 86.55,30.01 v2(86.55,29.32)
RXD_6: length 9.7
  TOP w0.102: U511.M10 v2(84.29,30.45)
  BOTTOM w0.102: v2(84.29,30.45) 84.29,30.99 84.74,31.44 85.57,31.44 86.21,32.08 86.21,33.47 87.09,34.36 87.09,37.03 86.78,37.35 R182.2
RXD_7: length 8.2
  TOP w0.102: U511.M11 v2(83.72,31.01)
  BOTTOM w0.102: v2(83.72,31.01) 83.72,31.55 85.52,33.36 85.52,35.68 84.3,36.9 R181.2
RXD_8: length 7.4
  TOP w0.102: U511.R7 88.2,29.88 91.29,32.97 91.29,33.47 90.9,33.86 v2(90.9,34.74)
  BOTTOM w0.102: v2(90.9,34.74) R180.2
RXD_9: length 8.9
  TOP w0.102: v2(91.41,36.78) 90.14,35.51 89.76,35.51 89.38,35.13 89.38,32.71 U511.R8
  BOTTOM w0.102: R179.2 v2(91.41,36.78)
RXD_10: length 10.3
  TOP w0.102: v2(85.99,29.88) 85.42,29.32 U511.M9
  BOTTOM w0.102: v2(85.99,29.88) 87.35,31.25 87.35,31.57 86.46,32.46 86.46,33.35 87.35,34.24 87.35,36.84 R178.2
RXD_11: length 9.7
  TOP w0.102: v2(90.4,36.52) 89.76,35.89 89.38,35.89 87.22,33.73 87.22,32.25 85.42,30.45 U511.N9
  BOTTOM w0.102: R177.2 v2(90.4,36.52)
RXIQ: length 9.7
  TOP w0.102: v2(81.38,36.65) 81.38,36.29 81.51,36.16 81.83,36.16 81.96,36.29 81.96,37.21 82.12,37.36 82.37,37.36 82.52,37.21 82.52,36.4 83.16,35.76 84.11,35.76 84.52,35.34 84.52,34.08 83.92,33.47 83.92,32.91 U511.P13
  BOTTOM w0.102: v2(81.38,36.65) 81.38,37.09 R176.2
SC_CAL_MUX0: length 45.7
  TOP w0.102: v1(57.63,36.9) 57.35,36.62 U15.6
  L5_SIG w0.114: v1(33.5,36.01) 34.01,35.51 35.02,35.51 35.66,36.14 v1(35.66,44.52)
  L6_SIG w0.114: v1(33.5,36.01) 33.5,36.78 34.77,38.05 39.98,38.05 40.23,38.3 47.98,38.3 50.39,35.89 53.31,35.89 53.95,35.25 54.84,35.25 55.34,35.76 56.49,35.76 v1(57.63,36.9)
  BOTTOM w0.102: v1(33.5,36.01) 34.64,34.87 35.28,34.87 35.46,35.05 U9.15 ; U8.15 36.35,46.48 35.66,45.79 v1(35.66,44.52)
SC_CAL_MUX1: length 42.4
  TOP w0.102: U15.5 57.85,35.85 v1(58.27,36.27)
  L5_SIG w0.114: v1(36.42,44.52) 36.12,44.22 v1(36.12,34.72)
  L6_SIG w0.114: v1(44.8,37.22) 47.92,37.22 48.49,36.65 48.49,35.76 48.74,35.51 52.93,35.51 54.58,33.86 57,33.86 57.38,34.24 57.38,35.38 v1(58.27,36.27)
  BOTTOM w0.102: v1(36.42,44.52) 36.42,45.92 37,46.5 U8.14 ; U9.14 36.11,34.72 v1(36.12,34.72) 36.84,34.72 37.2,35.08 42.91,35.08 43.53,35.7 43.53,36.46 44.3,37.22 v1(44.8,37.22)
SC_PD: length 34.3
  TOP w0.203: v1(46.58,57.99) 45.69,57.99 45.55,57.85 U3.20 ; v1(47.72,54.18) 47.46,54.44 U3.14 ; U4.14 47.46,42.5 47.6,42.36 47.6,40.59 v1(47.34,40.33) ; U4.20 45.55,45.91 v1(45.82,46.17)
  L5_SIG w0.114: v1(46.58,57.99) 47.22,57.35 47.22,54.68 v1(47.72,54.18) 47.09,53.54 46.58,53.54 43.66,50.62 43.66,49.45 43.03,48.82 43.03,47.95 43.41,47.57 45.44,47.57 45.82,47.19 v1(45.82,46.17) 45.82,45.09 47.34,43.57 v1(47.34,40.33)
  BOTTOM w0.102: v1(47.34,40.33) 48.82,40.33 R131.1 49.58,40.16 49.93,40.51 Q3.3
SCL: length 88.7
  TOP w0.102: U511.F14 78.63,28.76 78.06,28.76 v2(76.94,29.89) ; U15.23 56.2,33 v1(56.61,32.59) ; U20.7 v1(23.47,20.15)
  L6_SIG w0.114: v1(23.47,20.15) 22.96,20.66 22.96,21.28 23.21,21.54 23.85,21.54 24.1,21.28 26.01,21.28 26.52,21.79 29.18,21.79 29.44,22.04 34.64,22.04 36.04,23.44 39.98,23.44 40.69,22.73 42.72,22.73 42.9,22.55 v1(43.66,22.55) 43.98,22.87 44.78,22.87 46.57,21.08 48.16,21.08 50.58,23.51 56.3,23.51 56.81,24.01 v1(57.31,24.01) 57.76,24.46 59.79,24.46 60.42,23.82 65.12,23.82 67.03,21.92 69.95,21.92 73.89,25.85 75.16,25.85 76.93,27.63 76.93,28.27 77.32,28.65 77.32,29.5 v2(76.94,29.89)
  BOTTOM w0.102: U11.14 43.45,28.98 43.72,28.71 43.72,26.55 44.3,25.98 44.3,23.19 v1(43.66,22.55) ; v1(57.31,24.01) 58.2,24.9 58.2,27.51 57.09,28.62 57.09,30.97 56.81,31.25 56.3,31.25 56.11,31.44 56.11,32.08 v1(56.61,32.59) ; v2(76.94,29.89) 76.73,30.09 R211.2
SCLK: length 79.2
  TOP w0.102: v1(60.93,39.76) 60.49,39.32 59.22,39.32 58.58,39.95 57.95,39.95 56.74,41.16 56.74,42.87 57.43,43.56 U2.16 ; U511.E13 v2(78.63,27.06) ; v1(62.46,58.76) U14.17
  L5_SIG w0.114: v1(66.9,56.33) 66.9,54.05 67.79,53.16 67.79,39.19 66.27,37.67 62.46,37.67 61.98,38.14 61.98,38.71 v1(60.93,39.76) 60.42,39.25 60.42,38.24 59.85,37.67 59.85,34.94 60.42,34.36 60.42,25.09 61.31,24.2 64.23,24.2 64.68,23.76 64.68,22.87 65.76,21.79 68.68,21.79 73.94,27.06 v2(78.63,27.06)
  L6_SIG w0.114: v1(66.9,56.33) 65.89,57.35 64.87,57.35 63.46,58.76 v1(62.46,58.76)
SDA: length 89.1
  TOP w0.102: U20.8 23.85,20.65 v1(23.47,21.03) ; U15.22 v1(55.8,32.59) ; 79.2,28.19 v2(78.63,28.19)
  L6_SIG w0.114: v2(78.63,28.19) 76.81,26.36 76.17,26.36 75.31,25.5 74.04,25.5 70.08,21.54 66.9,21.54 65,23.44 58.9,23.44 v1(58.39,23.95) 57.88,23.44 56.61,23.44 56.36,23.19 50.77,23.19 48.35,20.76 45.64,20.76 45.38,21.03 44.42,21.03 v1(43.66,21.79) 42.39,20.52 41.76,20.52 39.98,22.3 38.58,22.3 37.82,23.06 36.29,23.06 34.14,20.9 32.1,20.9 31.6,21.41 26.64,21.41 25.75,20.52 23.98,20.52 v1(23.47,21.03)
  BOTTOM w0.102: R210.2 78.97,28.78 78.97,28.52 v2(78.63,28.19) ; v1(43.66,21.79) 44.17,22.3 44.17,22.62 44.61,23.06 44.61,26.17 44.04,26.74 44.04,29.41 43.82,29.63 U11.13 ; v1(55.8,32.59) 56.43,33.22 56.87,33.22 57.12,32.97 57.12,31.44 57.38,31.19 57.38,28.78 58.58,27.57 58.58,24.71 58.39,24.52 v1(58.39,23.95)
SDIO: length 79.1
  TOP w0.102: U14.18 62.73,58.26 v1(62.46,57.99) ; v1(60.93,38.81) 61.5,39.38 61.5,40.02 61.25,40.27 59.15,40.27 58.96,40.46 58.2,40.46 57.25,41.41 57.25,42.36 57.45,42.56 U2.18 ; U511.F12 v2(79.2,27.62)
  L5_SIG w0.114: v1(67.66,56.33) 67.66,55.19 68.11,54.75 68.11,38.97 66.48,37.35 62.01,37.35 61.57,37.79 61.57,38.62 61.38,38.81 v1(60.93,38.81) 60.93,38.11 60.17,37.35 60.17,35.25 60.81,34.62 60.81,25.28 61.5,24.58 64.49,24.58 65.12,23.95 65.12,23.06 65.89,22.3 68.43,22.3 72.74,26.62 73,26.62 73.82,27.44 77.88,27.44 78.07,27.62 v2(79.2,27.62)
  L6_SIG w0.114: v1(67.66,56.33) 67.16,55.83 66.52,55.83 66.27,56.08 66.27,56.46 65.76,56.97 64.74,56.97 63.73,57.99 v1(62.46,57.99)
STAT_DATA: length 75.6
  TOP w0.102: U15.21 55.4,32.96 55.22,32.78 v1(55.22,32.01)
  TOP w0.254: v1(101.12,62.91) 101.26,62.91 101.73,62.45
  L5_SIG w0.114: v1(55.22,32.01) 55.22,34.11 56.36,35.25 56.36,40.33 57.95,41.92 66.65,41.92 67.47,42.75 67.47,52.59 v1(65.63,54.43)
  L6_SIG w0.114: v1(101.12,62.91) 100.21,62.91 98.27,60.97 94.21,60.97 91.67,58.43 78.2,58.43 77.57,57.8 73.32,57.8 70.65,55.13 66.33,55.13 v1(65.63,54.43)
  BOTTOM w0.254: R196.2 100.71,62.91 v1(101.12,62.91)
STAT_POWER: length 73.2
  TOP w0.102: v1(54.65,32.59) 55,32.94 U15.20
  TOP w0.254: v1(100.18,62.05) 100.18,61.88 U21.14
  L5_SIG w0.114: v1(65.63,53.6) 66.01,53.6 67.22,52.4 67.22,42.94 66.52,42.24 57.82,42.24 55.98,40.4 55.98,36.4 54.33,34.74 54.33,34.11 54.65,33.79 v1(54.65,32.59)
  L6_SIG w0.114: v1(100.18,62.05) 98.72,60.59 94.27,60.59 91.8,58.12 78.34,58.12 77.7,57.48 73.45,57.48 70.78,54.81 66.84,54.81 v1(65.63,53.6)
  BOTTOM w0.254: R195.2 99.72,62.51 v1(100.18,62.05)
SUPPLY_NEG: length 109.6
  TOP w0.406: R160.2 12.36,8.84 R163.2 ; v1(57.06,27.89) 57.06,27.62 R139.1
  TOP w0.457: v1(10.44,8.46) C308.1 11.97,9.22 R163.2
  TOP w0.508: v1(10.44,8.46) 10.32,8.33 7.78,8.33 6.58,9.54 6.58,13.92 4.8,15.69 4.8,42.26 P1.7
  L5_SIG w0.508: v1(10.44,8.46) 11.97,8.46 12.36,8.07 18.9,8.07 20.48,9.66 30.26,9.66 31.21,8.71 40.1,8.71 41.76,10.36 46.96,10.36 47.6,11 47.6,13.15 50.26,15.82 52.42,15.82 53.31,16.71 55.47,16.71 56.36,17.6 56.36,26.68 57.06,27.38 v1(57.06,27.89)
SUPPLY_NEG_MONITOR: length 39.1
  TOP w0.102: A11.1 55.44,25.76 56.23,24.97 56.5,24.97 R136.2 56.74,24.73 56.74,23.7 57,23.44 59.03,23.44 v1(59.54,23.95) ; v1(59.08,52.52) 59.09,52.51 U2.71
  L5_SIG w0.114: v1(57.38,39.44) 57.38,37.92 57.12,37.67 57.12,36.14 57.63,35.63 57.63,32.59 58.14,32.08 58.14,31.32 57.63,30.81 57.63,28.9 58.65,27.89 58.65,24.84 v1(59.54,23.95)
  L6_SIG w0.114: v1(59.08,52.52) 59.08,51.94 58.27,51.13 58.27,43.13 57.12,41.98 57.12,40.21 57.38,39.95 v1(57.38,39.44)
SUPPLY_POS: length 44.4
  TOP w0.457: 12.1,14.81 R162.2 12.48,14.81 ; 12.1,14.81 v1(11.15,14.81) C297.1 ; 12.1,14.81 12.48,14.81 ; 12.48,14.81 13.89,14.81 R161.2
  BOTTOM w0.508: R137.1 11.15,14.28 v1(11.15,14.81) 10.51,15.44 6.2,15.44 4.42,17.22 4.42,42.24 5.74,43.56 8.64,43.56 P1.8
SUPPLY_POS_MONITOR: length 118.9
  TOP w0.102: U2.70 59.59,52.73 59.28,53.03 58.9,53.03 58.65,53.29 58.65,54.18 58.39,54.43 55.85,54.43 54.33,55.95 v1(54.33,56.46)
  L5_SIG w0.114: v1(3.53,49.6) 3.53,48.33 3.3,48.11 3.3,24.94 5.31,22.93 5.31,19.76 6.96,18.11 8.23,18.11 8.61,17.73 8.61,15.31 8.48,15.19 v1(8.48,14.42)
  L6_SIG w0.114: v1(54.33,56.46) 53.82,56.97 52.68,56.97 47.22,62.43 45.18,62.43 44.55,63.07 44.55,65.35 43.03,66.88 34.01,66.88 33.44,66.3 25.44,66.3 23.72,64.59 11.28,64.59 3.27,56.59 3.27,51.13 3.53,50.87 v1(3.53,49.6)
  BOTTOM w0.102: R138.1 10.37,13.8 9.41,14.76 8.82,14.76 v1(8.48,14.42)
  BOTTOM w0.305: R137.2 11.26,13.28 R138.1
TRIG_1: length 108.4
  TOP w0.102: U511.M12 v2(83.16,31.58) ; D19.3 v1(13.75,35.3)
  L6_SIG w0.114: v2(83.16,31.58) 80.5,31.58 78.97,30.05 77.95,30.05 77.57,30.43 76.55,30.43 76.3,30.17 76.3,28.78 76.55,28.52 76.55,27.76 75.03,26.24 73.76,26.24 69.82,22.3 67.16,22.3 65.25,24.2 60.55,24.2 59.92,24.84 57.12,24.84 56.11,23.82 50.33,23.82 47.9,21.4 46.7,21.4 44.14,23.95 43.41,23.95 42.52,23.06 41.12,23.06 40.36,23.82 35.91,23.82 35.15,23.06 30.2,23.06 29.56,23.7 27.66,23.7 26.39,22.43 25.5,22.43 24.87,21.79 22.58,21.79 22.33,22.04 21.18,22.04 19.78,20.65 19.78,18.23 18.9,17.35 17.88,17.35 16.23,19 16.23,32.83 v1(13.75,35.3)
  BOTTOM w0.102: v1(13.75,35.3) 15.07,33.98 16.74,33.98 16.99,34.24 16.99,36.27 17.88,37.16 RT10.2
TRIG_2: length 92.9
  TOP w0.102: D2.3 17.24,32.46 18.13,33.35 v1(19.02,33.35) ; U511.N12 v2(83.72,32.15)
  L6_SIG w0.114: v1(19.02,33.35) 18.15,32.47 18.15,27.24 18.64,26.74 20.17,26.74 21.69,25.22 24.61,25.22 25.37,24.46 27.28,24.46 27.66,24.08 29.69,24.08 30.33,23.44 35.02,23.44 35.79,24.2 40.49,24.2 41.3,23.39 42.4,23.39 43.34,24.33 44.61,24.33 46.52,22.43 48.42,22.43 50.14,24.14 55.92,24.14 57,25.22 60.04,25.22 60.68,24.58 65.38,24.58 66.65,23.31 70.33,23.31 73.63,26.62 74.9,26.62 75.54,27.25 75.54,28.27 75.92,28.65 75.92,30.3 76.44,30.82 77.68,30.82 78.06,30.44 78.98,30.44 80.62,32.08 81.89,32.08 82.4,32.59 83.28,32.59 v2(83.72,32.15)
  BOTTOM w0.102: v1(19.02,33.35) 19.66,33.98 19.66,35.38 18.64,36.4 18.64,37.68 RT1.1
TX_CLK: length 21.7
  TOP w0.102: R174.2 72.68,42.3 75.98,42.3 v2(76.81,43.13) ; U511.L12 v2(82.59,31.01)
  L5_SIG w0.114: v2(76.81,43.13) 77.7,42.24 78.46,42.24 78.84,41.86 78.84,36.65 81.25,34.24 81.25,32.35 v2(82.59,31.01)
TXD_0: length 26.6
  TOP w0.102: v2(70.71,49.03) 70.27,48.59 R171.1 ; U511.H12 v2(80.9,29.32)
  L5_SIG w0.114: v2(70.71,49.03) 71.54,49.03 74.14,46.43 74.14,43 74.78,42.36 75.41,42.36 77.7,40.08 77.7,35.25 80.11,32.84 80.11,30.1 v2(80.9,29.32)
TXD_1: length 25.1
  TOP w0.102: R172.1 v2(71.54,47.83) ; U511.G11 v2(80.89,28.19)
  L5_SIG w0.114: v2(71.54,47.83) 73.38,45.98 73.38,42.87 75.41,40.84 75.41,38.17 76.81,36.78 76.81,35.13 79.35,32.59 79.35,29.03 80.19,28.19 v2(80.9,28.19)
TXD_2: length 25.6
  TOP w0.102: v2(70.33,47.7) R170.1 ; U511.H13 v2(79.76,29.32)
  L5_SIG w0.114: v2(79.76,29.32) 79.76,32.68 77.19,35.25 77.19,40.08 75.35,41.92 74.84,41.92 73.76,43 73.76,46.37 71.73,48.4 71.03,48.4 v2(70.33,47.7)
TXD_3: length 24.3
  TOP w0.102: R169.1 v2(71.54,46.68) ; U511.G12 v2(80.33,27.62)
  L5_SIG w0.114: v2(80.33,27.62) 77.57,30.38 77.57,32.33 78.08,32.84 78.08,33.35 76.43,35 76.43,36.65 75.03,38.05 75.03,40.71 73,42.75 73,45.22 v2(71.54,46.68)
TXD_4: length 24.9
  TOP w0.102: U511.H14 79.19,29.88 78.49,30.59 78.17,30.59 76.93,31.82 74.27,31.82 v2(73.89,31.44) ; R168.1 v2(70.33,46.68)
  L5_SIG w0.114: v2(70.33,46.68) 70.97,46.05 70.97,45.29 71.35,44.9 71.73,44.9 72.24,44.4 72.24,42.49 73.63,41.09 73.63,36.9 73,36.27 73,35.51 73.51,35 73.51,31.82 v2(73.89,31.44)
TXD_5: length 24.8
  TOP w0.102: R167.1 v2(71.54,45.54) ; U511.G14 78.61,29.32 76.87,31.06 74.78,31.06 74.27,30.55 v2(73.89,30.55)
  L5_SIG w0.114: v2(71.54,45.54) 72.62,44.46 72.62,42.62 74.65,40.59 74.65,37.92 75.54,37.03 75.54,32.2 v2(73.89,30.55)
  BOTTOM w0.102: v2(73.89,30.55) 74.38,30.55 R217.2
TXD_6: length 24.7
  TOP w0.102: R114.1 v2(70.33,45.54) ; v2(72.24,33.09) 72.49,33.35 77.06,33.35 77.32,33.6 78.08,33.6 79.79,31.89 80.02,31.89 U511.K15
  L5_SIG w0.114: v2(70.33,45.54) 70.97,44.9 70.97,43.89 71.54,43.32 71.54,42.17 72.87,40.84 72.87,38.53 72.73,38.38 72.38,38.38 72.24,38.24 72.24,38.03 72.38,37.89 72.73,37.89 72.87,37.74 72.87,37.54 72.73,37.39 72.38,37.39 72.24,37.25 v2(72.24,33.09)
TXD_7: length 24.3
  TOP w0.102: U511.J15 79.76,31.03 79.41,31.38 79.22,31.38 78.59,32.01 77.57,32.01 77,32.59 73,32.59 v2(71.85,31.44) ; R113.1 v2(71.54,44.4)
  L5_SIG w0.114: v2(71.54,44.4) 71.85,44.08 71.85,42.36 73.25,40.97 73.25,37.28 72.62,36.65 72.62,34.62 73.12,34.11 73.12,32.97 72.11,31.95 72.11,31.7 v2(71.85,31.44)
TXD_8: length 24.5
  TOP w0.102: v2(70.84,32.33) 71.22,32.71 72.49,32.71 72.74,32.97 77.06,32.97 77.32,32.71 77.95,32.71 78.08,32.84 78.46,32.84 80.33,30.97 U511.J14 ; R112.1 v2(70.33,44.4)
  L5_SIG w0.114: v2(70.84,32.33) 70.84,32.71 70.71,32.84 70.71,40.71 69.82,41.6 69.82,42.24 70.33,42.75 v2(70.33,44.4)
TXD_9: length 24.3
  TOP w0.102: v2(72.87,31.44) 73.63,32.2 76.93,32.2 77.44,31.7 78.52,31.7 80.34,29.88 U511.J13 ; v2(71.09,43) 71.54,43.45 R109.1
  L5_SIG w0.114: v2(72.87,31.44) 72.38,30.95 71.71,30.95 71.35,31.32 71.35,32.71 71.73,33.09 71.73,41.48 71.09,42.11 71.09,42.99 v2(71.09,43)
TXD_10: length 24.9
  TOP w0.102: R111.1 70.2,43.25 70.9,42.56 71.41,42.56 71.98,43.12 v2(74.9,43.12) ; U511.J11 v2(82.03,29.32)
  L5_SIG w0.114: v2(74.9,43.12) 75.29,43.51 76.05,43.51 76.3,43.25 76.3,42.62 77.06,41.86 78.2,41.86 78.46,41.6 78.46,36.52 80.87,34.11 80.87,31.02 82.03,29.87 v2(82.03,29.32)
TXD_11: length 22
  TOP w0.102: v2(75.79,43.12) 75.35,42.68 72.11,42.68 R110.1 ; 81.46,28.19 v2(81.46,28.75)
  L5_SIG w0.114: v2(81.46,28.75) 81.46,29.33 80.49,30.3 80.49,32.97 78.08,35.38 78.08,40.21 75.79,42.49 v2(75.79,43.12)
TXIQ: length 24.8
  TOP w0.102: v2(71.22,33.47) 71.22,34.24 73.63,36.65 78.71,36.65 81.25,34.11 81.76,34.11 82.59,33.28 U511.N14 ; R175.2 v2(70.33,42.11)
  L5_SIG w0.114: v2(71.22,33.47) 71.22,34.49 71.35,34.62 71.35,41.09 v2(70.33,42.11)
UART_RX: length 42.6
  TOP w0.102: 81.46,22.53 v2(82.03,22.53) ; P510.1 57.63,2.99 57.38,3.25 57.38,5.03 57.76,5.41 v1(57.76,6.17)
  L5_SIG w0.114: v1(57.76,6.17) 57.76,6.63 57.93,6.8 58.65,6.8 59.92,5.53 63.09,5.53 64.49,6.93 64.49,8.84 66.39,10.74 66.39,13.28 67.03,13.92 67.03,16.08 68.68,17.73 72.24,17.73 76.81,22.3 78.97,22.3 80.75,24.08 81.04,24.08 82.03,23.09 v2(82.03,22.53)
UART_TX: length 48.2
  TOP w0.102: P510.3 59.66,2.11 59.41,1.85 57.76,1.85 57,2.61 57,7.95 v1(57.76,8.71) ; U511.B7 v2(79.76,22.53)
  L5_SIG w0.114: v1(57.76,8.71) 57,7.95 57,6.04 57.88,5.15 63.35,5.15 65.89,7.69 65.89,9.22 66.77,10.11 66.77,13.03 67.41,13.66 67.41,15.95 68.81,17.35 72.36,17.35 76.93,21.92 79.15,21.92 v2(79.76,22.53)
UNNAMED_16_ADP5074_I189_COMP: length 2.7
  TOP w0.102: C182.1 54.84,21.35 54.84,21.15 v2(54.59,20.9)
  TOP w0.203: U10.7 v2(54.59,20.9)
  BOTTOM w0.102: v2(54.59,20.9) 54.59,20.32 R1.2
UNNAMED_16_ADP5074_I189_FB: length 11.7
  TOP w0.203: v2(53.95,20.9) 54.09,20.65 U10.8
  BOTTOM w0.203: v2(53.95,20.9) 52.55,20.9 50.65,19 50.65,16.43 49.76,15.54 49.76,14.42 50.06,14.12 R7.2 R10.1
UNNAMED_16_ADP5074_I189_SLEW: length 1.8
  TOP w0.102: v1(57.25,18.49) 57.13,18.37 U10.2
  BOTTOM w0.102: R8.1 57.25,17.8 v1(57.25,18.49)
UNNAMED_16_ADP5074_I189_SS: length 1.5
  TOP w0.102: U10.5 55.59,20.38 56.18,20.98 R2.1
UNNAMED_16_ADP5074_I189_SW: length 2.9
  TOP w0.305: 56.34,17.46 U10.1 56.99,17.87
  TOP w1.016: 63.61,14.04 D24.C 64.75,13.28
UNNAMED_16_ADP5074_I189_VREF: length 7.4
  TOP w0.305: C6.1 v1(52.3,19.76) 52.68,19.76 53.07,19.37 U10.9
  BOTTOM w0.203: R7.1 50.52,15.54 51.15,16.18 51.15,18.62 v1(52.3,19.76)
UNNAMED_16_ADP5074_I189_VREG: length 1.8
  TOP w0.102: U10.11 51.84,18.37 C3.1
UNNAMED_16_ADP7182V2_I221_ADJ: length 2.6
  TOP w0.102: U13.3 41.94,17.73 R78.1 41.63,16.48 41.65,16.46 R77.2
UNNAMED_16_ADP7182V2_I221_VOUT: length 5.5
  TOP w0.305: U13.1 U13.2 42.41,18.23 ; U13.1 42.41,18.73 ; U13.1 43.12,19.14
  TOP w0.457: 42.9,19.71 C218.1 42.36,20.21 ; 41.63,18.78 R78.2 42.14,18.28
  TOP w0.508: 42.15,20.01 E19.1 41.6,19.4
UNNAMED_16_CAP_I180_N1: length 1
  BOTTOM w0.102: C1.1 56.16,20.14 R1.1
UNNAMED_16_CAP_I199_N1: length 6.6
  TOP w0.406: 61.52,11.63 C8.1 ; C8.1 62.02,12.16 ; C8.1 62.02,11.1 ; 60.08,10.61 R9.1 59.58,11.12
  TOP w0.635: 61.19,13.28 D24.A ; D24.A 61.87,12.66 ; D24.A 61.87,13.9
  TOP w1.016: 60.65,13.03 L4.1 59.88,11.67
UNNAMED_16_CAP_I236_N1: length 1.6
  BOTTOM w0.102: C328.1 18.07,48.4 17.94,48.53 VR1.3
UNNAMED_29_CN30PODDEVENV2_I44_1: length 7.2
  BOTTOM w0.102: P1.16 11.58,34.67 12.8,35.89 14.07,35.89 15.34,34.62 RT11.1
UNNAMED_29_CN30PODDEVENV2_I44_2: length 6.5
  BOTTOM w0.102: P1.18 11.07,32.13 11.4,32.46 14.58,32.46 14.96,32.08 RT12.1
UNNAMED_29_CN30PODDEVENV2_I44_3: length 6.6
  BOTTOM w0.102: RT13.1 14.7,29.54 14.2,29.03 11.53,29.03 10.97,29.59 P1.20
UNNAMED_29_CN30PODDEVENV2_I44_4: length 6.3
  BOTTOM w0.102: P1.22 12.11,27.05 12.29,26.87 15.96,26.87 RT14.1
UNNAMED_29_CN30PODDEVENV2_I44_5: length 6.2
  BOTTOM w0.102: P1.24 9.96,24.46 RT15.1
UNNAMED_29_CN30PODDEVENV2_I44_6: length 6.2
  BOTTOM w0.102: P1.26 16.03,21.97 RT16.1
UNNAMED_29_CN30PODDEVENV2_I44_7: length 6.2
  BOTTOM w0.102: RT17.1 16.03,19.43 P1.28
UNNAMED_29_CN30PODDEVENV2_I44_8: length 6.8
  BOTTOM w0.102: P1.30 10.62,17.6 14.32,17.6 15.09,16.84 RT18.1
UNNAMED_29_CN30PODDEVENV2_I44_N: length 6.2
  BOTTOM w0.102: P1.14 9.96,37.16 RT10.1
UNNAMED_29_CN30PODDEVENV2_I45_1: length 9.7
  BOTTOM w0.102: RT2.2 14.7,35.89 14.07,36.52 12.67,36.52 12.04,35.89 8.59,35.89 P1.15
UNNAMED_29_CN30PODDEVENV2_I45_2: length 9.2
  BOTTOM w0.102: P1.17 8.59,33.35 RT3.2
UNNAMED_29_CN30PODDEVENV2_I45_3: length 9.2
  BOTTOM w0.102: P1.19 8.59,30.81 RT4.2
UNNAMED_29_CN30PODDEVENV2_I45_4: length 9.2
  BOTTOM w0.102: P1.21 8.59,28.27 RT5.2
UNNAMED_29_CN30PODDEVENV2_I45_5: length 9.5
  BOTTOM w0.102: RT6.2 13.11,25.73 12.73,26.11 11.02,26.11 10.64,25.73 8.59,25.73 P1.23
UNNAMED_29_CN30PODDEVENV2_I45_6: length 9.5
  BOTTOM w0.102: RT7.2 15.96,23.06 14.82,23.06 14.44,22.68 11.15,22.68 10.77,23.06 8.46,23.06 P1.25
UNNAMED_29_CN30PODDEVENV2_I45_7: length 9.4
  BOTTOM w0.102: P1.27 8.59,20.65 12.93,20.65 13.18,20.39 14.58,20.39 14.83,20.65 RT8.2
UNNAMED_29_CN30PODDEVENV2_I45_8: length 9.2
  BOTTOM w0.102: P1.29 8.59,18.11 RT9.2
UNNAMED_29_CN30PODDEVENV2_I45_N: length 9.2
  BOTTOM w0.102: P1.13 8.59,38.43 RT1.2
UNNAMED_30_AD9963_I47_AUXADCREF: length 1.9
  TOP w0.203: v1(57,50.62) 57.12,50.56 57.12,50.56 U2.2
  BOTTOM w0.102: C63.1 57.57,50.04 v1(57,50.62)
UNNAMED_30_AD9963_I47_AUXIN1: length 2.4
  TOP w0.102: R3.2 R4.1 58.59,52.38 U2.72
UNNAMED_30_AD9963_I47_DLLFILT: length 4.2
  TOP w0.102: R15.1 70.59,52.65 C64.1
  TOP w0.203: R15.1 69.31,52.14 68.17,52.14 67.68,51.65 U2.54
UNNAMED_30_AD9963_I47_RXBIAS: length 1.9
  TOP w0.203: R13.1 56.54,48.71 57.25,48.71 57.4,48.56 U2.6
UNNAMED_30_AD9963_I47_TRXCLK: length 31.7
  TOP w0.102: v2(67.09,40.97) 67.09,40.4 67.28,40.21 68.68,40.21 68.79,40.31 68.79,40.6 68.63,40.76 68.12,40.76 67.09,41.8 U2.36
  L6_SIG w0.114: v2(85.32,38.55) 85.32,38.94 85.03,39.22 85.03,39.43 85.27,39.67 85.27,39.87 85.12,40.02 84.92,40.02 84.68,39.78 84.47,39.78 84.33,39.92 84.33,40.13 84.57,40.37 84.57,40.57 84.42,40.72 84.22,40.72 83.98,40.48 83.77,40.48 83.54,40.71 70.2,40.71 68.83,42.08 68.53,42.08 68.3,41.86 68.3,41.22 68.81,40.71 68.81,40.46 68.43,40.08 68.04,40.08 67.79,40.33 67.79,41.6 67.66,41.73 67.41,41.73 67.09,41.41 v2(67.09,40.97)
  BOTTOM w0.102: R173.2 v2(85.32,38.55)
UNNAMED_30_AD9963_I47_TRXD0: length 37.2
  TOP w0.102: U2.32 65.09,40.88 65.89,40.08 65.89,39.19 v2(65.5,38.81)
  L6_SIG w0.114: v2(86.33,36.52) 86.08,36.27 85.82,36.27 84.68,37.41 78.08,37.41 77.7,37.03 72.48,37.03 72.33,37.18 72.33,37.65 72.19,37.79 71.98,37.79 71.83,37.65 71.83,37.18 71.69,37.03 71.48,37.03 71.34,37.18 71.34,37.65 71.19,37.79 70.99,37.79 70.84,37.65 70.84,37.18 70.7,37.03 70.49,37.03 70.35,37.18 70.35,37.65 70.2,37.79 70,37.79 69.85,37.65 69.85,37.18 69.71,37.03 69.5,37.03 69.36,37.18 69.36,37.65 69.21,37.79 69.01,37.79 68.86,37.65 68.86,37.18 68.72,37.03 68.51,37.03 68.37,37.18 68.37,37.65 68.22,37.79 68.02,37.79 67.87,37.65 67.87,37.18 67.73,37.03 67.52,37.03 67.38,37.18 67.38,37.65 67.23,37.79 67.03,37.79 66.88,37.65 66.88,37.18 66.74,37.03 66.53,37.03 66.39,37.18 66.39,38.16 66.24,38.3 66.04,38.3 65.89,38.16 65.89,37.18 65.75,37.03 65.38,37.03 65.14,37.27 65.14,38.45 v2(65.5,38.81)
  BOTTOM w0.102: v2(86.33,36.52) R188.1
UNNAMED_30_AD9963_I47_TRXD1: length 32
  TOP w0.102: U2.31 64.59,40.74 v2(65.5,39.82)
  L6_SIG w0.114: v2(83.54,38.55) 83.03,38.05 81.13,38.05 80.74,38.43 80.49,38.43 80.24,38.17 79.98,38.17 79.6,38.55 79.35,38.55 78.97,38.17 78.79,38.17 78.64,38.32 78.64,39.04 78.5,39.19 78.29,39.19 78.15,39.04 78.15,38.32 78,38.17 77.8,38.17 77.65,38.32 77.65,39.04 77.51,39.19 77.3,39.19 77.16,39.04 77.16,38.01 76.93,37.79 75.66,37.79 74.79,38.67 74.79,39.04 74.65,39.19 74.44,39.19 74.3,39.04 74.3,38.57 74.15,38.43 73.95,38.43 73.8,38.57 73.8,39.04 73.66,39.19 73.45,39.19 73.31,39.04 73.31,38.32 73.16,38.17 72.96,38.17 72.81,38.32 72.81,39.04 72.67,39.19 72.46,39.19 72.32,39.04 72.32,38.7 72.17,38.55 71.97,38.55 71.82,38.7 71.82,39.04 71.68,39.19 71.47,39.19 71.33,39.04 71.33,38.7 71.18,38.55 67.16,38.55 65.89,39.82 v2(65.5,39.82)
  BOTTOM w0.102: v2(83.54,38.55) 83.54,38.17 83.35,37.98 R187.1
UNNAMED_30_AD9963_I47_TRXD2: length 34.5
  TOP w0.102: U2.30 64.09,40.48 v2(64.74,39.82)
  L6_SIG w0.114: v2(89.63,36.52) 89.13,37.03 88.62,37.03 88.36,36.78 88.36,36.27 88.53,36.1 88.53,35.8 88.36,35.63 86.59,35.63 86.46,35.76 86.46,36.01 86.84,36.4 86.84,36.65 86.46,37.03 85.57,37.03 84.81,37.79 77.7,37.79 77.32,37.41 75.2,37.41 75.05,37.56 75.05,37.9 74.91,38.05 74.7,38.05 74.56,37.9 74.56,37.56 74.41,37.41 74.21,37.41 74.06,37.56 74.06,37.9 73.92,38.05 73.71,38.05 73.57,37.9 73.57,37.56 73.42,37.41 73.12,37.41 72.39,38.15 66.93,38.15 65.76,39.32 65.25,39.32 v2(64.74,39.82)
  BOTTOM w0.102: R186.1 89.63,36.21 v2(89.63,36.52)
UNNAMED_30_AD9963_I47_TRXD3: length 35.6
  TOP w0.102: U2.29 63.59,39.96 v2(64.74,38.81)
  L6_SIG w0.114: v2(64.74,38.81) 64.74,37.16 65.25,36.65 77.95,36.65 78.34,37.04 84.55,37.04 86.33,35.25 90.52,35.25 90.78,35.51 90.78,35.76 90.51,36.02 89.37,36.02 v2(88.87,36.52)
  BOTTOM w0.102: v2(88.87,36.52) R185.1
